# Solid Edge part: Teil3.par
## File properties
Author: administrator
Template: Normal.par
Last saved by: administrator
Revision: 1
Application: Solid Edge
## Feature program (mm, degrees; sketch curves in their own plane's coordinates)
sketch for "unnamed Protrusion 1" plane through (0, 0, 0) normal (0, -1, 0) x-axis (1, 0, 0)
  line (-36.2267, 12.9333) -> (-36.2267, 32.9333)
  line (-36.2267, 32.9333) -> (43.7733, 32.9333)
  line (43.7733, 32.9333) -> (43.7733, 12.9333)
  line (43.7733, 12.9333) -> (13.7733, 12.9333)
  line (13.7733, 12.9333) -> (13.7733, -7.0667)
  line (13.7733, -7.0667) -> (-6.2267, -7.0667)
  line (-6.2267, -7.0667) -> (-6.2267, 12.9333)
  line (-6.2267, 12.9333) -> (-36.2267, 12.9333)
extrude "unnamed Protrusion 1" add finite 20 symmetric
